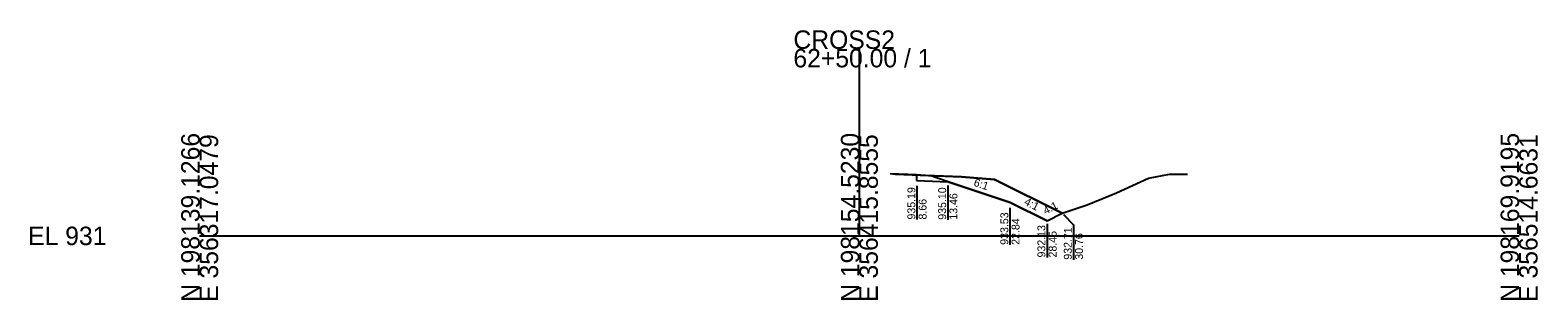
# Model space of a CAD drawing. Extents: x -26 to 203, y -10 to 14021.
# Drawn here: x -25.7 to 202.8, y 3490.3 to 3531.2 of the extents above; entities that cross this region are included whole.
import ezdxf

# ---------------------------------------------------------------- set-up
doc = ezdxf.new("R2010")
doc.units = 0
for name, color, linetype in [('Default', 7, 'Continuous'), ('P_E_XS_Ground', 7, 'Continuous'), ('P_XS', 7, 'Continuous'), ('P_XS_EAR_CommonGrnd', 7, 'Continuous'), ('P_XS_Lane', 7, 'Continuous'), ('P_XS_Rock', 7, 'Continuous')]:
    doc.layers.add(name, color=color, linetype=linetype)

msp = doc.modelspace()

# ---------------------------------------------------------------- linework, layer by layer
at = {"layer": 'Default'}
for p, q in [((100, 3500), (100, 3528.34)), ((0, 3500), (100, 3500)), ((100, 3500), (200, 3500))]:
    msp.add_line(p, q, dxfattribs=at)
at = {"layer": 'P_E_XS_Ground'}
for p, q in [((104.66, 3509.45), (105.46, 3509.35)), ((105.46, 3509.35), (115.5, 3508.95)), ((115.5, 3508.95), (120.5, 3508.55)), ((120.5, 3508.55), (130.76, 3503.42)), ((138.98, 3506.51), (143.83, 3508.73)), ((143.83, 3508.73), (147.03, 3509.36)), ((147.03, 3509.36), (149.74, 3509.37)), ((134.55, 3504.7), (138.98, 3506.51)), ((130.76, 3503.42), (134.55, 3504.7))]:
    msp.add_line(p, q, dxfattribs=at)
at = {"layer": 'P_XS'}
for p, q in [((104.66, 3509.45), (108.66, 3509.29)), ((108.66, 3509.29), (110.66, 3509.13)), ((113.46, 3508.2), (110.66, 3509.13))]:
    msp.add_line(p, q, dxfattribs=at)
at = {"layer": 'P_XS_EAR_CommonGrnd'}
msp.add_lwpolyline([(108.66, 3508.39), (113.46, 3508.2), (122.84, 3505.07), (128.45, 3502.26), (130.76, 3503.42), (120.5, 3508.55), (115.5, 3508.95), (108.66, 3509.22)], close=True, dxfattribs=at)
at = {"layer": 'P_XS_Lane'}
for p, q in [((108.66, 3509.22), (108.66, 3508.39)), ((108.66, 3508.39), (113.46, 3508.2)), ((122.84, 3505.07), (113.46, 3508.2)), ((128.45, 3502.26), (122.84, 3505.07)), ((128.45, 3502.26), (130.76, 3503.42))]:
    msp.add_line(p, q, dxfattribs=at)
at = {"layer": 'P_XS_Rock'}
for p, q in [((108.73, 3507.59), (108.73, 3502.48)), ((113.4, 3507.66), (113.4, 3502.45)), ((122.82, 3504.25), (122.82, 3498.65)), ((128.44, 3501.83), (128.44, 3496.73)), ((130.94, 3503.23), (132.44, 3501.68)), ((132.44, 3501.68), (132.44, 3496.39))]:
    msp.add_line(p, q, dxfattribs=at)

# ---------------------------------------------------------------- texts
at = {"layer": 'Default'}
for s, p in [('CROSS2', (90, 3528.34)), ('62+50.00 / 1', (90, 3525.54)), ('EL 931', (-26, 3498.6))]:
    msp.add_text(s, height=2.8, dxfattribs=at).set_placement(p)
for s, p in [('N 198139.1266', (0, 3490)), ('E 356317.0479', (2.8, 3490)), ('N 198154.5230', (100, 3490)), ('E 356415.8555', (102.8, 3490)), ('N 198169.9195', (200, 3490)), ('E 356514.6631', (202.8, 3490))]:
    msp.add_text(s, height=2.8, rotation=90, dxfattribs=at).set_placement(p)
at = {"layer": 'P_XS_Rock'}
for s, rotation, p in [('6:1', 341.5651, (117.23, 3507.61)), ('935.19', 90, (108.48, 3502.48)), ('935.10', 90, (113.15, 3502.45)), ('13.46', 90, (114.85, 3502.45)), ('8.66', 90, (110.18, 3502.48)), ('933.53', 90, (122.57, 3498.65)), ('4:1', 333.4349, (124.86, 3504.79)), ('4:1', 26.5651, (128.22, 3503.21)), ('22.84', 90, (124.27, 3498.65)), ('932.13', 90, (128.19, 3496.73)), ('932.71', 90, (132.19, 3496.39)), ('28.45', 90, (129.89, 3496.73)), ('30.76', 90, (133.89, 3496.39))]:
    msp.add_text(s, height=1.2, rotation=rotation, dxfattribs=at).set_placement(p)

doc.saveas('drawing.dxf')
